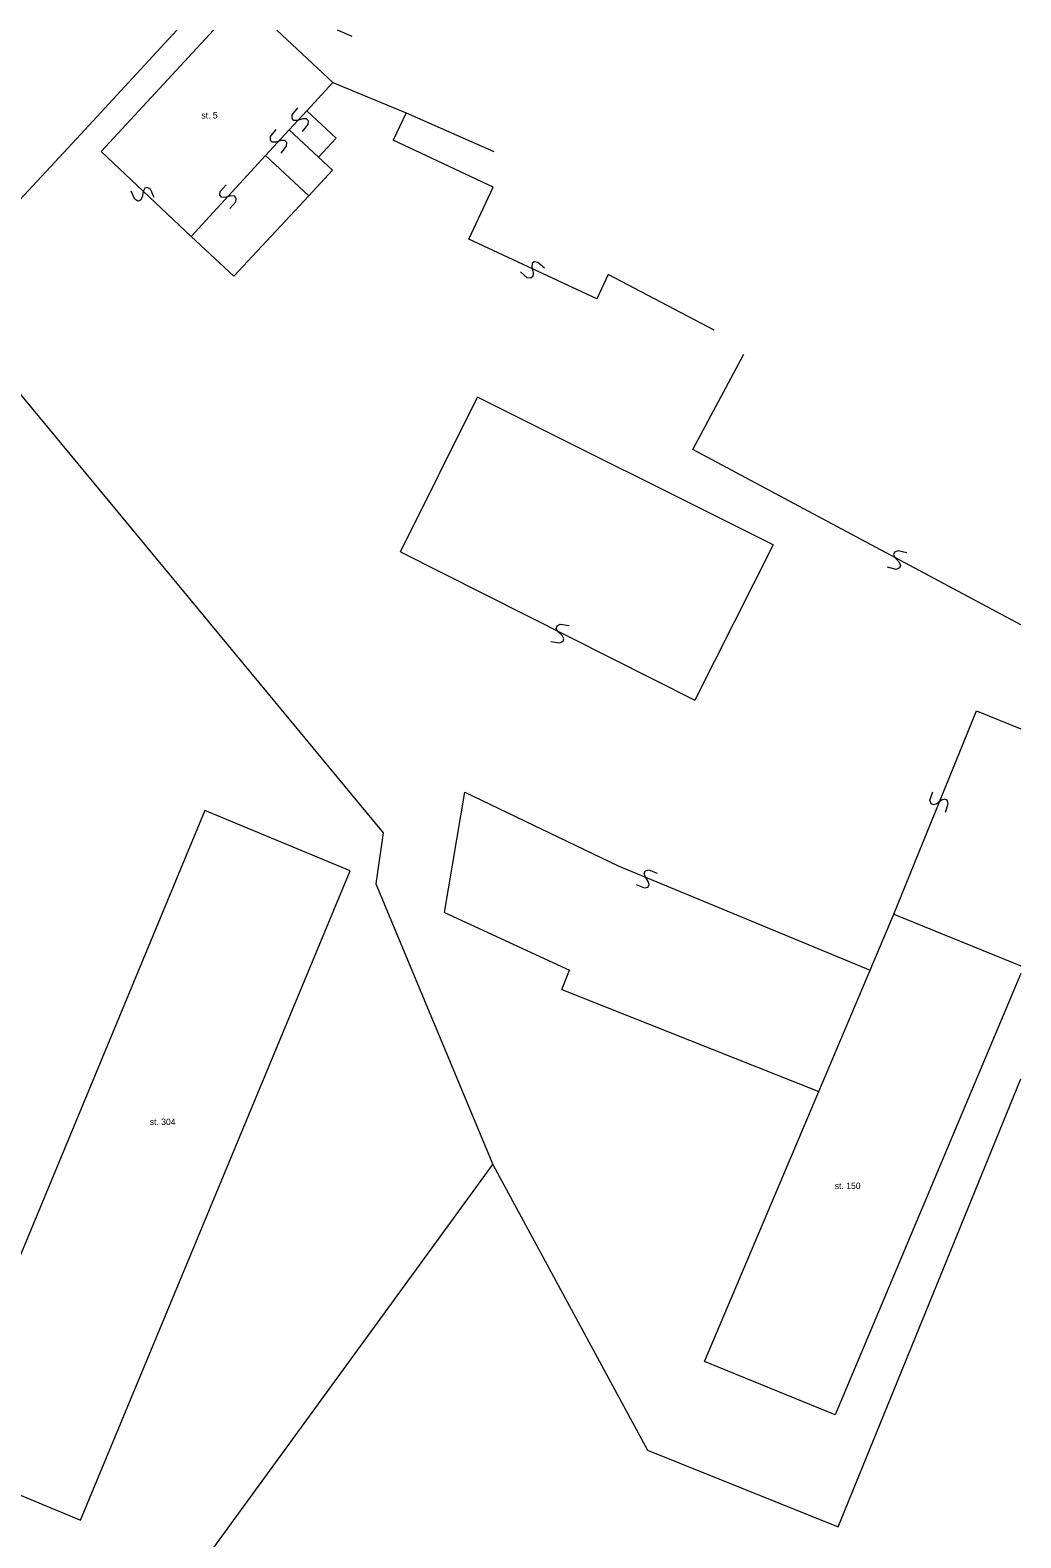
# Model space of a CAD drawing. Extents: x -694702 to -694000, y -1089746 to -1089192.
# Drawn here: x -694370.8 to -694293.6, y -1089533.7 to -1089416.3 of the extents above; entities that cross this region are included whole.
import ezdxf

# ---------------------------------------------------------------- set-up
doc = ezdxf.new("R2010")
doc.units = 0
doc.header["$LTSCALE"] = 0.2
doc.layers.add('50', color=7, linetype='Continuous', lineweight=13)
doc.layers.add('52', color=7, linetype='Continuous', lineweight=13)

msp = doc.modelspace()

# ---------------------------------------------------------------- linework, layer by layer
at = {"layer": '50'}
for p, q in [((-694356.49, -1089416.29), (-694365.24, -1089425.75)), ((-694351.57, -1089416.29), (-694347.21, -1089420.36)), ((-694345.7, -1089416.79), (-694346.83, -1089416.29)), ((-694349.24, -1089422.57), (-694347.21, -1089420.36)), ((-694347.21, -1089420.36), (-694341.5, -1089422.73)), ((-694350.61, -1089424.06), (-694349.24, -1089422.57)), ((-694349.24, -1089422.57), (-694346.95, -1089424.7)), ((-694341.5, -1089422.73), (-694342.5, -1089424.86)), ((-694341.5, -1089422.73), (-694334.66, -1089425.734)), ((-694352.44, -1089426.05), (-694350.61, -1089424.06)), ((-694350.61, -1089424.06), (-694348.33, -1089426.19)), ((-694365.24, -1089425.75), (-694358.23, -1089432.35)), ((-694358.23, -1089432.35), (-694352.44, -1089426.05)), ((-694347.24, -1089427.2), (-694349.08, -1089429.18)), ((-694358.23, -1089432.35), (-694354.91, -1089435.44)), ((-694319.16, -1089448.94), (-694315.186, -1089441.524)), ((-694341.94, -1089456.91), (-694335.93, -1089444.87)), ((-694312.9, -1089456.37), (-694335.93, -1089444.87)), ((-694293.62, -1089462.61), (-694319.16, -1089448.94)), ((-694312.9, -1089456.37), (-694319, -1089468.47)), ((-694341.94, -1089456.91), (-694319, -1089468.47)), ((-694303.52, -1089485.13), (-694297.07, -1089469.29)), ((-694297.07, -1089469.29), (-694293.62, -1089470.7)), ((-694338.5, -1089485.01), (-694336.93, -1089475.63)), ((-694336.93, -1089475.63), (-694324.98, -1089481.36)), ((-694324.98, -1089481.36), (-694305.36, -1089489.49)), ((-694343.85, -1089482.76), (-694334.75, -1089504.62)), ((-694338.5, -1089485.01), (-694328.77, -1089489.48)), ((-694329.37, -1089491), (-694328.77, -1089489.48)), ((-694329.37, -1089491), (-694309.36, -1089498.94)), ((-694307.85, -1089532.85), (-694293.62, -1089497.96)), ((-694358.38, -1089537.05), (-694334.75, -1089504.62)), ((-694334.75, -1089504.62), (-694322.7, -1089526.87)), ((-694322.7, -1089526.87), (-694307.85, -1089532.85))]:
    msp.add_line(p, q, dxfattribs=at)
for points in [[(-694359.36, -1089416.29), (-694366.82, -1089424.38), (-694378.43, -1089436.85)], [(-694346.95, -1089424.7), (-694348.33, -1089426.19), (-694347.24, -1089427.2)], [(-694336.61, -1089432.56), (-694334.71, -1089428.51), (-694342.5, -1089424.86)], [(-694352.44, -1089426.05), (-694349.08, -1089429.18), (-694354.91, -1089435.44)], [(-694317.498, -1089439.649), (-694325.75, -1089435.31), (-694326.64, -1089437.22), (-694336.61, -1089432.56)], [(-694378.43, -1089436.85), (-694376.79, -1089438.33), (-694343.28, -1089478.8), (-694343.85, -1089482.76)], [(-694318.27, -1089519.98), (-694309.36, -1089498.94), (-694305.36, -1089489.49), (-694303.52, -1089485.13), (-694293.62, -1089489.16)], [(-694293.62, -1089489.75), (-694308.08, -1089524.13), (-694318.27, -1089519.98)]]:
    msp.add_lwpolyline(points, dxfattribs=at)
msp.add_lwpolyline([(-694378.17, -1089527.62), (-694366.86, -1089532.32), (-694345.84, -1089481.77), (-694357.16, -1089477.06)], close=True, dxfattribs=at)
at = {"layer": '52'}
for points in [[(-694349.56, -1089424.183), (-694349.124, -1089423.634), (-694349.11, -1089423.349), (-694349.246, -1089423.199), (-694349.53, -1089423.199), (-694349.958, -1089423.327), (-694350.236, -1089423.319), (-694350.378, -1089423.177), (-694350.372, -1089422.885), (-694349.929, -1089422.343)], [(-694351.237, -1089425.868), (-694350.807, -1089425.315), (-694350.796, -1089425.029), (-694350.934, -1089424.881), (-694351.218, -1089424.884), (-694351.644, -1089425.016), (-694351.922, -1089425.012), (-694352.066, -1089424.871), (-694352.063, -1089424.579), (-694351.625, -1089424.032)], [(-694361.11, -1089429.315), (-694361.406, -1089428.68), (-694361.655, -1089428.54), (-694361.85, -1089428.594), (-694361.977, -1089428.849), (-694362.054, -1089429.288), (-694362.185, -1089429.534), (-694362.376, -1089429.597), (-694362.634, -1089429.461), (-694362.92, -1089428.822)], [(-694355.218, -1089430.187), (-694354.762, -1089429.655), (-694354.737, -1089429.371), (-694354.867, -1089429.216), (-694355.151, -1089429.205), (-694355.584, -1089429.317), (-694355.861, -1089429.299), (-694355.998, -1089429.152), (-694355.981, -1089428.86), (-694355.517, -1089428.335)], [(-694330.724, -1089434.835), (-694331.247, -1089434.371), (-694331.532, -1089434.341), (-694331.689, -1089434.469), (-694331.704, -1089434.753), (-694331.6, -1089435.187), (-694331.622, -1089435.464), (-694331.772, -1089435.598), (-694332.063, -1089435.576), (-694332.58, -1089435.104)], [(-694302.505, -1089456.992), (-694303.186, -1089456.832), (-694303.451, -1089456.941), (-694303.528, -1089457.128), (-694303.407, -1089457.385), (-694303.109, -1089457.717), (-694302.997, -1089457.972), (-694303.065, -1089458.161), (-694303.332, -1089458.28), (-694304.011, -1089458.11)], [(-694330.221, -1089463.886), (-694329.53, -1089463.997), (-694329.274, -1089463.87), (-694329.209, -1089463.678), (-694329.348, -1089463.43), (-694329.669, -1089463.12), (-694329.798, -1089462.874), (-694329.744, -1089462.68), (-694329.486, -1089462.543), (-694328.797, -1089462.664)], [(-694299.495, -1089477.2), (-694299.272, -1089476.536), (-694299.356, -1089476.263), (-694299.534, -1089476.168), (-694299.801, -1089476.265), (-694300.16, -1089476.53), (-694300.424, -1089476.617), (-694300.606, -1089476.532), (-694300.7, -1089476.255), (-694300.467, -1089475.595)], [(-694323.591, -1089482.832), (-694322.941, -1089483.092), (-694322.663, -1089483.024), (-694322.558, -1089482.851), (-694322.64, -1089482.578), (-694322.885, -1089482.205), (-694322.958, -1089481.937), (-694322.862, -1089481.76), (-694322.581, -1089481.682), (-694321.935, -1089481.951)]]:
    msp.add_lwpolyline(points, dxfattribs=at)

# ---------------------------------------------------------------- texts
for s, p in [('st. 5', (-694357.44, -1089423.17)), ('st. 304', (-694361.46, -1089501.55)), ('st. 150', (-694308.11, -1089506.54))]:
    msp.add_text(s, height=0.5, dxfattribs=at).set_placement(p)

doc.saveas('drawing.dxf')
